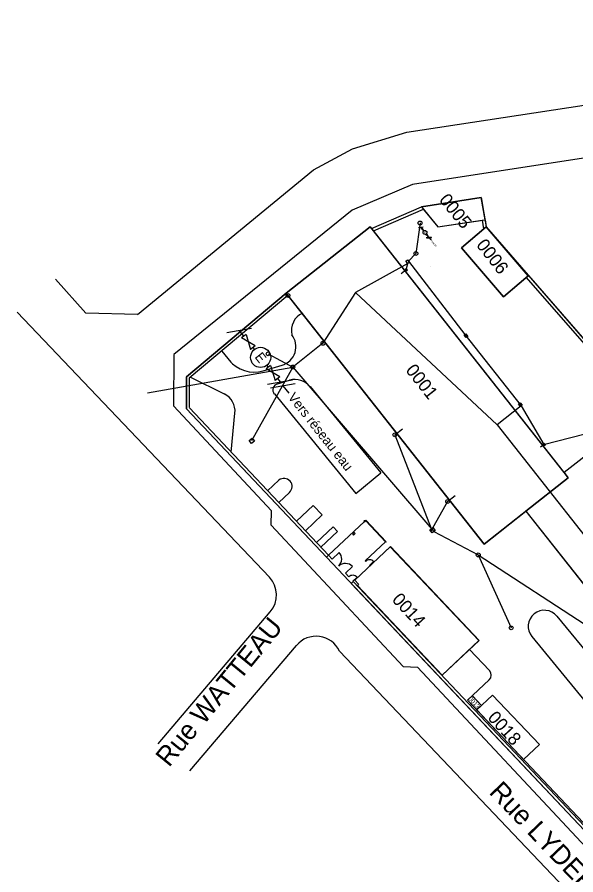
# Model space of a CAD drawing. Extents: x 704421 to 705059, y 7058908 to 7059523.
# Drawn here: x 704420.6 to 704507.1, y 7058975.5 to 7059108.3 of the extents above; entities that cross this region are included whole.
import ezdxf

# ---------------------------------------------------------------- set-up
doc = ezdxf.new("R2010")
doc.units = 0
for name, color, linetype in [('DH_HACHURE-MOTIF', 7, 'Continuous'), ('DH_TEXTE', 7, 'Continuous'), ('GO_A DEMOLIR', 7, 'Continuous'), ('GO_MUR_EXTERIEUR', 7, 'Continuous'), ('IMM_LIMITE PHYSIQUE', 7, 'Continuous'), ('R_PLU_CANALISATION_CL_A', 7, 'Continuous'), ('RES_EAU BASSE PRESSION', 7, 'Continuous'), ('RES_EAU BASSE PRESSION - EQUIP - TEXTE', 7, 'Continuous'), ('RES_INCENDIE - EQUIP - TEXTE', 7, 'Continuous'), ('SID_NUMERO_BATI', 7, 'Continuous'), ('SID_POLYLIGNES_BATI', 7, 'Continuous'), ('SID_POLYLIGNES_IMMEUBLE', 7, 'Continuous'), ('SO_EP_EQUIP', 7, 'Continuous'), ('VOIRIE_BORDURE', 7, 'Continuous'), ('VOIRIE_ROUTE', 7, 'Continuous')]:
    doc.layers.add(name, color=color, linetype=linetype)

msp = doc.modelspace()

# ---------------------------------------------------------------- linework, layer by layer
at = {"layer": 'DH_HACHURE-MOTIF'}
for p, q in [((704492.8, 7059075.53), (704493.18, 7059075.86)), ((704493.18, 7059075.86), (704499.68, 7059068.26)), ((704489.38, 7059072.6), (704492.8, 7059075.53)), ((704495.88, 7059065.01), (704489.38, 7059072.6))]:
    msp.add_line(p, q, dxfattribs=at)
for points in [[(704492.56, 7059076.86), (704493, 7059076.93), (704492.42, 7059080.39), (704483.15, 7059078.96), (704483.48, 7059078.55), (704485.7, 7059075.83), (704492.56, 7059076.86)], [(704462.47, 7059065.21), (704464.67, 7059062.42), (704492.86, 7059026.7), (704499.33, 7059031.81), (704505.89, 7059036.98), (704505.27, 7059037.77), (704475.53, 7059075.46), (704475.23, 7059075.84), (704462.2, 7059065.56), (704462.47, 7059065.21)], [(704499.68, 7059068.26), (704499.34, 7059067.97), (704495.88, 7059065.01)], [(704551.65, 7058991.33), (704511.27, 7059042.51), (704505.27, 7059037.77), (704505.89, 7059036.98), (704499.33, 7059031.81), (704539.09, 7058981.42), (704551.65, 7058991.33)], [(704491.09, 7059003.13), (704491.03, 7059003.2), (704490.3, 7059002.52), (704491.72, 7059001.01), (704492.45, 7059001.7), (704491.09, 7059003.13)]]:
    msp.add_lwpolyline(points, dxfattribs=at)
for points in [[(704488.34, 7059008.23), (704492.06, 7059011.74), (704478.34, 7059026.29), (704472.82, 7059021.09), (704473.4, 7059020.47), (704473.24, 7059020.31), (704486.38, 7059006.38)], [(704494.17, 7059003.32), (704491.72, 7059001.01), (704498.96, 7058993.34), (704501.41, 7058995.65)]]:
    msp.add_lwpolyline(points, close=True, dxfattribs=at)
at = {"layer": 'GO_A DEMOLIR'}
for points in [[(704493.18, 7059075.86), (704489.38, 7059072.6), (704495.88, 7059065.01), (704499.68, 7059068.26)], [(704494.17, 7059003.32), (704491.72, 7059001.01), (704498.96, 7058993.34), (704501.41, 7058995.65)]]:
    msp.add_lwpolyline(points, close=True, dxfattribs=at)
at = {"layer": 'GO_MUR_EXTERIEUR'}
for p, q in [((704492.42, 7059080.39), (704483.15, 7059078.96)), ((704493, 7059076.93), (704492.42, 7059080.39)), ((704483.15, 7059078.96), (704485.7, 7059075.83)), ((704462.2, 7059065.56), (704475.23, 7059075.84)), ((704475.23, 7059075.84), (704505.89, 7059036.98)), ((704485.7, 7059075.83), (704493, 7059076.93)), ((704493.18, 7059075.86), (704489.38, 7059072.6)), ((704499.68, 7059068.26), (704493.18, 7059075.86)), ((704489.38, 7059072.6), (704495.88, 7059065.01)), ((704489.38, 7059072.6), (704489.38, 7059072.6)), ((704495.88, 7059065.01), (704499.68, 7059068.26)), ((704492.86, 7059026.7), (704462.2, 7059065.56)), ((704511.27, 7059042.51), (704505.27, 7059037.77)), ((704505.27, 7059037.77), (704505.89, 7059036.98)), ((704505.89, 7059036.98), (704492.86, 7059026.7)), ((704505.89, 7059036.98), (704499.33, 7059031.81)), ((704499.33, 7059031.81), (704539.09, 7058981.42)), ((704478.38, 7059026.33), (704472.82, 7059021.09)), ((704492.1, 7059011.78), (704478.38, 7059026.33)), ((704486.38, 7059006.38), (704492.1, 7059011.78)), ((704490.3, 7059002.52), (704491.03, 7059003.2)), ((704491.03, 7059003.2), (704492.45, 7059001.7)), ((704491.72, 7059001.01), (704490.3, 7059002.52)), ((704492.45, 7059001.7), (704491.72, 7059001.01))]:
    msp.add_line(p, q, dxfattribs=at)
msp.add_lwpolyline([(704472.82, 7059021.09), (704473.4, 7059020.47), (704473.24, 7059020.31), (704486.38, 7059006.38)], dxfattribs=at)
msp.add_lwpolyline([(704494.17, 7059003.32), (704501.41, 7058995.65), (704498.96, 7058993.34), (704491.72, 7059001.01)], close=True, dxfattribs=at)
at = {"layer": 'IMM_LIMITE PHYSIQUE'}
for p, q in [((704475.44, 7059075.59), (704483.17, 7059078.92)), ((704475.74, 7059075.23), (704483.48, 7059078.56)), ((704492.56, 7059076.86), (704492.78, 7059075.51)), ((704493, 7059076.93), (704493.18, 7059075.86)), ((704499.39, 7059068.01), (704511.13, 7059054.48)), ((704499.74, 7059068.3), (704511.28, 7059054.99)), ((704462.2, 7059065.56), (704446.77, 7059052.59)), ((704462.49, 7059065.21), (704447.22, 7059052.38)), ((704446.77, 7059052.59), (704446.77, 7059047.64)), ((704447.22, 7059052.38), (704447.22, 7059047.84)), ((704446.77, 7059047.64), (704468.44, 7059024.66)), ((704447.24, 7059047.8), (704468.77, 7059024.97)), ((704468.77, 7059024.97), (704474.33, 7059030.22)), ((704474.42, 7059024.09), (704477.63, 7059027.12)), ((704469.32, 7059024.39), (704470.41, 7059025.42)), ((704468.77, 7059024.97), (704468.44, 7059024.66)), ((704468.77, 7059024.97), (704469.32, 7059024.39)), ((704474.42, 7059024.09), (704474.48, 7059024.02)), ((704471.38, 7059022.2), (704472.47, 7059023.23)), ((704475.75, 7059023.99), (704475.1, 7059023.37)), ((704475.1, 7059023.37), (704475.15, 7059023.31)), ((704471.38, 7059022.2), (704471.93, 7059021.62)), ((704473.2, 7059021.58), (704472.55, 7059020.97)), ((704472.61, 7059020.9), (704472.28, 7059020.59)), ((704472.28, 7059020.59), (704535.98, 7058953.07)), ((704472.55, 7059020.97), (704472.61, 7059020.9)), ((704472.61, 7059020.9), (704536.21, 7058953.48))]:
    msp.add_line(p, q, dxfattribs=at)
for points in [[(704474.49, 7059030.37), (704474.25, 7059030.31), (704474.42, 7059030.13)], [(704474.49, 7059030.37), (704477.65, 7059027.02), (704477.69, 7059027.05), (704474.53, 7059030.4)], [(704472.46, 7059028.31), (704472.66, 7059028.09), (704472.9, 7059028.32), (704472.7, 7059028.53)]]:
    msp.add_lwpolyline(points, close=True, dxfattribs=at)
for centre, radius, start, end in [((704469.32, 7059024.39), 1.5, 313.3307, 43.3307), ((704475.1, 7059023.37), 0.9, 43.3307, 133.3307), ((704471.38, 7059022.2), 1.5, 43.3307, 133.3307), ((704472.55, 7059020.97), 0.9, 43.3307, 133.3307)]:
    msp.add_arc(centre, radius, start, end, dxfattribs=at)
at = {"layer": 'R_PLU_CANALISATION_CL_A'}
for p, q in [((704482.94, 7059076.44), (704482.3, 7059071.72)), ((704482.3, 7059071.72), (704481.13, 7059070.52)), ((704480.77, 7059069.17), (704481.05, 7059070.14)), ((704481.13, 7059070.52), (704489.9, 7059059.16)), ((704480.77, 7059069.17), (704480.02, 7059068.58)), ((704472.95, 7059065.69), (704494.89, 7059045.16)), ((704459.43, 7059056.17), (704463.25, 7059054.13)), ((704440.73, 7059050.13), (704463.25, 7059054.13)), ((704479.04, 7059043.63), (704480.22, 7059044.57)), ((704479.04, 7059043.63), (704484.68, 7059029.11)), ((704502.04, 7059042.07), (704501.57, 7059041.71)), ((704487.21, 7059033.29), (704488.39, 7059034.22)), ((704487.21, 7059033.29), (704484.63, 7059028.69)), ((704491.95, 7059025.02), (704497.04, 7059013.73))]:
    msp.add_line(p, q, dxfattribs=at)
for points in [[(704480.74, 7059070.53), (704480.98, 7059070.71), (704481.28, 7059070.32), (704481.05, 7059070.14), (704480.74, 7059070.53)], [(704481.05, 7059070.14), (704472.95, 7059065.69), (704467.91, 7059057.8)], [(704489.78, 7059059.07), (704490.02, 7059059.25), (704490.33, 7059058.86), (704490.09, 7059058.68), (704489.78, 7059059.07)], [(704489.9, 7059059.16), (704498.62, 7059048.1), (704502.13, 7059042.11)], [(704572.09, 7059059.65), (704568.59, 7059059.11), (704502.04, 7059042.07)], [(704467.91, 7059057.8), (704463.25, 7059054.13), (704456.87, 7059042.67)], [(704463.25, 7059054.13), (704485.05, 7059028.64), (704491.95, 7059025.02), (704509.56, 7059013.59)], [(704498.62, 7059048.1), (704494.89, 7059045.16), (704515.8, 7059018.65), (704509.56, 7059013.59)], [(704498.2, 7059048.4), (704498.43, 7059048.59), (704498.74, 7059048.2), (704498.51, 7059048.01), (704498.2, 7059048.4)], [(704457.31, 7059042.63), (704456.84, 7059042.26), (704456.47, 7059042.73), (704456.94, 7059043.1), (704457.31, 7059042.63)], [(704485.29, 7059028.82), (704484.82, 7059028.45), (704484.45, 7059028.92), (704484.92, 7059029.29), (704485.29, 7059028.82)]]:
    msp.add_lwpolyline(points, dxfattribs=at)
for centre in [(704482.94, 7059076.44), (704483.7, 7059074.98), (704482.3, 7059071.72), (704462.49, 7059065.21), (704467.91, 7059057.8), (704459.43, 7059056.17), (704463.25, 7059054.13), (704479.04, 7059043.63), (704487.21, 7059033.29), (704491.95, 7059025.02), (704497.04, 7059013.73)]:
    msp.add_circle(centre, 0.3, dxfattribs=at)
at = {"layer": 'RES_EAU BASSE PRESSION'}
for p, q in [((704453.05, 7059059.47), (704456.87, 7059060.15)), ((704457.06, 7059057.14), (704457.3, 7059056.85)), ((704459.46, 7059054.1), (704459.23, 7059054.4)), ((704459.35, 7059051.48), (704463.17, 7059052.16)), ((704460.85, 7059052.34), (704461.26, 7059051.82))]:
    msp.add_line(p, q, dxfattribs=at)
at = {"layer": 'RES_EAU BASSE PRESSION - EQUIP - TEXTE'}
for p, q in [((704455.67, 7059058.91), (704454.96, 7059059.81)), ((704456.02, 7059059.19), (704455.32, 7059058.63)), ((704457.42, 7059057.42), (704455.32, 7059058.63)), ((704456.02, 7059059.19), (704456.71, 7059056.86)), ((704457.42, 7059057.42), (704456.71, 7059056.86)), ((704459.81, 7059054.38), (704459.11, 7059053.83)), ((704461.21, 7059052.62), (704459.11, 7059053.83)), ((704459.81, 7059054.38), (704460.5, 7059052.06)), ((704461.21, 7059052.62), (704460.5, 7059052.06)), ((704461.72, 7059051.23), (704462.65, 7059050.06))]:
    msp.add_line(p, q, dxfattribs=at)
msp.add_circle((704458.26, 7059055.62), 1.56, dxfattribs=at)
at = {"layer": 'RES_INCENDIE - EQUIP - TEXTE'}
for p, q in [((704482.69, 7059075.73), (704483.43, 7059075.86)), ((704483.2, 7059075.62), (704483.06, 7059075.79)), ((704483.27, 7059075.67), (704483.13, 7059075.56)), ((704483.54, 7059075.33), (704483.13, 7059075.56)), ((704483.27, 7059075.67), (704483.4, 7059075.22)), ((704483.54, 7059075.33), (704483.4, 7059075.22)), ((704483.47, 7059075.27), (704483.51, 7059075.22)), ((704484, 7059074.74), (704483.86, 7059074.63)), ((704484.27, 7059074.4), (704483.86, 7059074.63)), ((704483.93, 7059074.69), (704483.89, 7059074.75)), ((704484, 7059074.74), (704484.13, 7059074.29)), ((704483.91, 7059074.18), (704484.65, 7059074.31)), ((704484, 7059074.07), (704484.74, 7059074.2)), ((704484.27, 7059074.4), (704484.13, 7059074.29)), ((704484.2, 7059074.35), (704484.28, 7059074.25)), ((704484.37, 7059074.13), (704484.59, 7059073.85)), ((704484.57, 7059069.64), (704484.57, 7059069.64)), ((704459.81, 7059050.9), (704463.63, 7059051.57))]:
    msp.add_line(p, q, dxfattribs=at)
msp.add_circle((704483.7, 7059074.98), 0.301, dxfattribs=at)
at = {"layer": 'SID_POLYLIGNES_BATI'}
for p, q in [((704492.42, 7059080.39), (704483.15, 7059078.96)), ((704493, 7059076.93), (704492.42, 7059080.39)), ((704483.15, 7059078.96), (704485.7, 7059075.83)), ((704462.2, 7059065.56), (704475.23, 7059075.84)), ((704475.23, 7059075.84), (704505.89, 7059036.98)), ((704485.7, 7059075.83), (704493, 7059076.93)), ((704493.18, 7059075.86), (704489.38, 7059072.6)), ((704499.68, 7059068.26), (704493.18, 7059075.86)), ((704489.38, 7059072.6), (704495.88, 7059065.01)), ((704489.38, 7059072.6), (704489.38, 7059072.6)), ((704495.88, 7059065.01), (704499.68, 7059068.26)), ((704492.86, 7059026.7), (704462.2, 7059065.56)), ((704511.27, 7059042.51), (704505.27, 7059037.77)), ((704505.27, 7059037.77), (704505.89, 7059036.98)), ((704505.89, 7059036.98), (704492.86, 7059026.7)), ((704505.89, 7059036.98), (704499.33, 7059031.81)), ((704499.33, 7059031.81), (704539.09, 7058981.42)), ((704478.34, 7059026.29), (704472.82, 7059021.09)), ((704492.06, 7059011.74), (704478.34, 7059026.29)), ((704486.38, 7059006.38), (704492.06, 7059011.74)), ((704490.3, 7059002.52), (704491.03, 7059003.2)), ((704491.03, 7059003.2), (704492.45, 7059001.7)), ((704491.72, 7059001.01), (704490.3, 7059002.52)), ((704492.45, 7059001.7), (704491.72, 7059001.01))]:
    msp.add_line(p, q, dxfattribs=at)
msp.add_lwpolyline([(704472.82, 7059021.09), (704473.4, 7059020.47), (704473.24, 7059020.31), (704486.38, 7059006.38)], dxfattribs=at)
msp.add_lwpolyline([(704494.17, 7059003.32), (704501.41, 7058995.65), (704498.96, 7058993.34), (704491.72, 7059001.01)], close=True, dxfattribs=at)
at = {"layer": 'SID_POLYLIGNES_IMMEUBLE'}
for p, q in [((704446.77, 7059047.64), (704446.77, 7059052.59)), ((704535.98, 7058953.07), (704446.77, 7059047.64))]:
    msp.add_line(p, q, dxfattribs=at)
for points in [[(704475.23, 7059075.84), (704475.44, 7059075.59), (704483.17, 7059078.92), (704483.15, 7059078.96), (704492.42, 7059080.39)], [(704492.42, 7059080.39), (704493.18, 7059075.86), (704511.28, 7059054.99)], [(704446.77, 7059052.59), (704462.2, 7059065.56), (704475.23, 7059075.84)]]:
    msp.add_lwpolyline(points, dxfattribs=at)
at = {"layer": 'SO_EP_EQUIP'}
for centre in [(704480.77, 7059069.17), (704502.13, 7059042.11)]:
    msp.add_circle(centre, 0.2, dxfattribs=at)
at = {"layer": 'VOIRIE_BORDURE'}
for p, q in [((704452.23, 7059056.59), (704453.65, 7059054.86)), ((704457.91, 7059053.34), (704457.91, 7059053.34)), ((704458.66, 7059053.56), (704461.57, 7059054.41)), ((704447.41, 7059052.54), (704452.63, 7059049.96)), ((704460.88, 7059051.54), (704462.75, 7059052.08)), ((704465.91, 7059051.11), (704476.88, 7059037.72)), ((704460.39, 7059049.95), (704473.01, 7059034.55)), ((704453.69, 7059040.96), (704454.29, 7059046.98)), ((704473.01, 7059034.55), (704476.88, 7059037.72)), ((704459.35, 7059034.95), (704461.09, 7059036.59)), ((704461.07, 7059033.14), (704462.72, 7059034.7)), ((704463.81, 7059030.23), (704466.4, 7059032.66)), ((704467.77, 7059031.21), (704466.4, 7059032.66)), ((704465.19, 7059028.77), (704467.77, 7059031.21)), ((704466.9, 7059026.95), (704469.48, 7059029.39)), ((704470.17, 7059028.66), (704469.48, 7059029.39)), ((704467.59, 7059026.22), (704470.17, 7059028.66)), ((704504.13, 7059015.53), (704523.58, 7058991.8)), ((704500.26, 7059012.37), (704519.71, 7058988.63)), ((704490.61, 7059010.37), (704493.7, 7059007.1)), ((704493.65, 7059005.68), (704490.3, 7059002.52)), ((704490.3, 7059002.52), (704508.23, 7058983.51))]:
    msp.add_line(p, q, dxfattribs=at)
for centre, radius, start, end in [((704466.02, 7059059.78), 3, 115.4761, 192.4737), ((704460.73, 7059057.29), 3, 286.3025, 37.942), ((704457.25, 7059058.35), 5, 219.5679, 286.3025), ((704463.58, 7059049.2), 3, 39.3307, 106.0656), ((704461.15, 7059050.58), 1, 106.0656, 219.3307), ((704451.3, 7059047.27), 3, 354.3306, 63.7442), ((704461.88, 7059035.63), 1.25, 312.1096, 129.3307), ((704502.19, 7059013.95), 2.5, 39.3307, 219.3307), ((704492.97, 7059006.41), 1, 313.3306, 43.3306)]:
    msp.add_arc(centre, radius, start, end, dxfattribs=at)
at = {"layer": 'VOIRIE_ROUTE'}
for p, q in [((704459.61, 7059021.56), (704420.57, 7059062.63)), ((704439.21, 7059062.29), (704431.18, 7059062.49)), ((704444.83, 7059056.07), (704444.78, 7059048.12)), ((704444.78, 7059048.12), (704459.96, 7059031.86)), ((704459.89, 7059029.65), (704459.96, 7059031.86)), ((704459.89, 7059029.65), (704480.35, 7059007.72)), ((704442.38, 7058995.75), (704459.76, 7059016.22)), ((704447.3, 7058991.57), (704463.81, 7059011.01)), ((704527.18, 7058950.47), (704470.47, 7059010.13)), ((704480.35, 7059007.72), (704482.59, 7059007.66)), ((704482.54, 7059007.66), (704534.87, 7058951.59))]:
    msp.add_line(p, q, dxfattribs=at)
for points in [[(704439.21, 7059062.29), (704466.43, 7059084.66), (704472.47, 7059087.95), (704480.92, 7059090.49), (704597.81, 7059108.33)], [(704599.06, 7059100.45), (704481.77, 7059082.41), (704472.42, 7059078.45), (704444.83, 7059056.07)], [(704431.18, 7059062.49), (704426.51, 7059067.73)]]:
    msp.add_lwpolyline(points, dxfattribs=at)
for centre, start, end in [((704456.71, 7059018.81), 319.6675, 43.547), ((704466.85, 7059008.42), 25.2763, 139.6675)]:
    msp.add_arc(centre, 4, start, end, dxfattribs=at)

# ---------------------------------------------------------------- texts
at = {"layer": 'DH_TEXTE'}
for s, rotation, p in [('Rue WATTEAU', 50.7423, (704444.08, 7058992.02)), ('Rue LYDERIC', 313.8024, (704493.48, 7058988.15))]:
    msp.add_text(s, height=3, rotation=rotation, dxfattribs=at).set_placement(p)
at = {"layer": 'RES_EAU BASSE PRESSION - EQUIP - TEXTE'}
for s, p in [('E', (704457.27, 7059055.66)), ('Vers réseau eau', (704462.4, 7059049.44))]:
    msp.add_text(s, height=1.5, rotation=308.2727, dxfattribs=at).set_placement(p)
at = {"layer": 'RES_INCENDIE - EQUIP - TEXTE'}
for s, p in [('E', (704483.51, 7059074.99)), ('Vers BI', (704484.53, 7059073.74))]:
    msp.add_text(s, height=0.29, rotation=308.2727, dxfattribs=at).set_placement(p)
at = {"layer": 'SID_NUMERO_BATI'}
for s, height, rotation, p in [('0005', 2, 309.3307, (704485.78, 7059079.97)), ('0006', 2, 307.9879, (704491.55, 7059073)), ('0001', 2, 308.2727, (704480.61, 7059053.6)), ('0014', 2, 312.5129, (704478.48, 7059018.01)), ('0013', 0.698, 312.5129, (704490.34, 7059002.7)), ('0018', 2, 312.5129, (704493.29, 7058999.72))]:
    msp.add_text(s, height=height, rotation=rotation, dxfattribs=at).set_placement(p)

doc.saveas('drawing.dxf')
